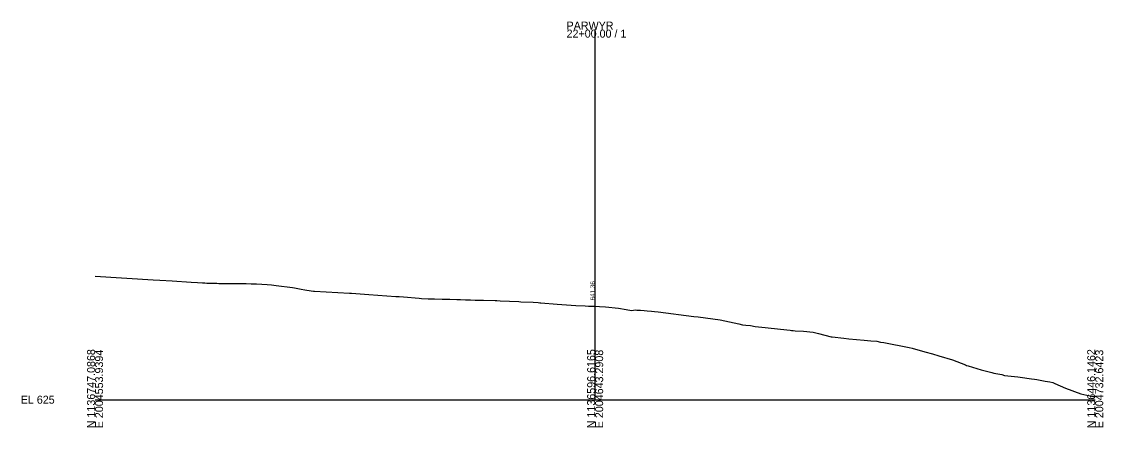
# Model space of a CAD drawing. Extents: x -2173 to 2007764, y -181 to 1138563.
# Drawn here: x -1982.6 to -1604.1, y 2990.3 to 3132.3 of the extents above; entities that cross this region are included whole.
import ezdxf

# ---------------------------------------------------------------- set-up
doc = ezdxf.new("R2010")
doc.units = 0
for name, color, linetype in [('Default', 7, 'Continuous'), ('RD_PD_Final_TrvlWay', 7, 'Continuous'), ('RD_PD_MedBWall', 7, 'Continuous'), ('RD_XS_TX_Elev_EX', 7, 'Continuous')]:
    doc.layers.add(name, color=color, linetype=linetype)

msp = doc.modelspace()

# ---------------------------------------------------------------- linework, layer by layer
at = {"layer": 'RD_PD_Final_TrvlWay'}
msp.add_lwpolyline([(-1956.9, 3043.18), (-1936.53, 3042), (-1934.27, 3041.86), (-1929.93, 3041.57), (-1923.23, 3041.11), (-1921.02, 3040.98), (-1919.29, 3040.88), (-1918.54, 3040.85), (-1917.8, 3040.82), (-1917.01, 3040.8), (-1914.32, 3040.75), (-1913.55, 3040.72), (-1912.41, 3040.69), (-1911.36, 3040.69), (-1908.24, 3040.72), (-1906.98, 3040.72), (-1905.59, 3040.7), (-1904.03, 3040.66), (-1902.29, 3040.6), (-1900.42, 3040.52), (-1898.49, 3040.42), (-1896.68, 3040.31), (-1895.21, 3040.19), (-1893.56, 3040), (-1887.81, 3039.24), (-1887.14, 3039.1), (-1884.77, 3038.69), (-1883.44, 3038.47), (-1882.78, 3038.35), (-1880.41, 3038.04), (-1880.06, 3038), (-1867.83, 3037.29), (-1867.18, 3037.25), (-1861.15, 3036.81), (-1851.59, 3036.16), (-1850.81, 3036.12), (-1850.45, 3036.1), (-1848.96, 3036), (-1843.49, 3035.51), (-1842.69, 3035.47), (-1840.35, 3035.32), (-1838.13, 3035.25), (-1835.4, 3035.21), (-1832.7, 3035.16), (-1830.35, 3035.12), (-1829.03, 3035.07), (-1827.29, 3034.95), (-1825.56, 3034.92), (-1823.93, 3034.82), (-1820.92, 3034.82), (-1816.9, 3034.67), (-1816.32, 3034.66), (-1815.13, 3034.59), (-1808.57, 3034.35), (-1807.85, 3034.3), (-1803.63, 3034.11), (-1801.87, 3034), (-1801.3, 3033.93), (-1800.94, 3033.91), (-1795.2, 3033.46), (-1791.88, 3033.17), (-1790.34, 3033.1), (-1788.69, 3032.92), (-1785.35, 3032.89), (-1784.2, 3032.77), (-1781.9, 3032.73), (-1780.4, 3032.65), (-1778.26, 3032.45), (-1773.68, 3032), (-1771.09, 3031.58), (-1769.21, 3031.22), (-1767.81, 3031.4), (-1767.36, 3031.38), (-1767.01, 3031.37), (-1766.06, 3031.29), (-1764.73, 3031.21), (-1763.73, 3031.13), (-1762.2, 3030.98), (-1761.15, 3030.86), (-1759.83, 3030.71), (-1747.33, 3029.13), (-1745.85, 3028.95), (-1738.12, 3028), (-1731.65, 3026.51), (-1730.36, 3026.23), (-1729.12, 3026.05), (-1727.55, 3026), (-1725.92, 3025.64), (-1722.45, 3025.23), (-1716.99, 3024.63), (-1713.66, 3024.28), (-1713.18, 3024.23), (-1712.56, 3024.18), (-1711.95, 3024.14), (-1709.04, 3024), (-1705.65, 3023.6), (-1705.15, 3023.46), (-1703.72, 3023.19), (-1699.3, 3022), (-1698.92, 3021.96), (-1694.85, 3021.52), (-1693.1, 3021.33), (-1687.74, 3020.79), (-1685.4, 3020.58), (-1683.33, 3020.44), (-1682.03, 3020.14), (-1680.91, 3020), (-1672.02, 3018.24), (-1670.93, 3018), (-1666.51, 3016.8), (-1663.81, 3016), (-1661.69, 3015.37), (-1656.82, 3014), (-1652.33, 3012.18), (-1651.91, 3012), (-1651.39, 3011.83), (-1646.8, 3010.47), (-1643.11, 3009.51), (-1642.44, 3009.33), (-1641.63, 3009.12), (-1639.64, 3008.79), (-1638.67, 3008.5), (-1634, 3008), (-1633.15, 3007.9), (-1629.25, 3007.31), (-1628.18, 3007.22), (-1627.33, 3007.1), (-1624.37, 3006.53), (-1622.84, 3006.27), (-1621.75, 3006), (-1621.04, 3005.67), (-1617.26, 3004), (-1611.96, 3002), (-1607.71, 3001.15), (-1606.9, 3001.12)], dxfattribs=at)
at = {"layer": 'RD_PD_MedBWall'}
for p, q in [((-1781.9, 3000), (-1781.9, 3129.53)), ((-1956.9, 3000), (-1781.9, 3000)), ((-1781.9, 3000), (-1606.9, 3000))]:
    msp.add_line(p, q, dxfattribs=at)

# ---------------------------------------------------------------- texts
at = {"layer": 'Default'}
msp.add_text('-', height=0.0001, dxfattribs=at).set_placement((-1956.9, 3000))
at = {"layer": 'RD_PD_MedBWall'}
for s, p in [('PARWYR', (-1791.9, 3129.53)), ('22+00.00 / 1', (-1791.9, 3126.73)), ('EL 625', (-1982.9, 2998.6))]:
    msp.add_text(s, height=2.8, dxfattribs=at).set_placement(p)
for s, p in [('N 1136747.0868', (-1956.9, 2990)), ('E 2004553.9394', (-1954.1, 2990)), ('N 1136596.6165', (-1781.9, 2990)), ('E 2004643.2908', (-1779.1, 2990)), ('N 1136446.1462', (-1606.9, 2990)), ('E 2004732.6423', (-1604.1, 2990))]:
    msp.add_text(s, height=2.8, rotation=90, dxfattribs=at).set_placement(p)
at = {"layer": 'RD_XS_TX_Elev_EX'}
msp.add_text('641.36', height=1.6, rotation=90, dxfattribs=at).set_placement((-1782, 3034.73))

doc.saveas('drawing.dxf')
